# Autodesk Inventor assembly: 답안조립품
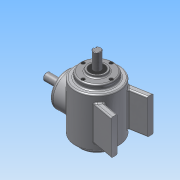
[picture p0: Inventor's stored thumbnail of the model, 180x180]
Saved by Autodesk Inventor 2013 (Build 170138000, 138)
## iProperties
Created: 2015-01
Part Number: 답안조립품
Document SubType Name: Assembly
Designer: Administrator
Author: Administrator
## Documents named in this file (15)
- C:\Users\Administrator\Desktop\450106V1009\답안조립품.iam
- C:\Users\Administrator\Desktop\450106V1009\1-본체.ipt
- C:\Users\Administrator\Desktop\450106V1009\커버.ipt
- C:\Users\Administrator\Desktop\450106V1009\베어링 6203.ipt
- C:\Users\Administrator\Desktop\450106V1009\서브 축.ipt
- 서브 축.ipt
- C:\Users\Administrator\Desktop\450106V1009\키 4x4.ipt
- C:\Users\Administrator\Desktop\450106V1009\서브 베벨기어.ipt
- C:\Users\Administrator\Desktop\450106V1009\메인 축.ipt
- 메인 축.ipt
- C:\Users\Administrator\Desktop\450106V1009\키 5x5.ipt
- C:\Users\Administrator\Desktop\450106V1009\메인 베벨기어.ipt
- C:\Users\Administrator\Desktop\450106V1009\커버2.ipt
- C:\Users\Administrator\Desktop\450106V1009\오일실.ipt
- C:\Users\Administrator\Desktop\450106V1009\M4.ipt
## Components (13 placed, 2 different names)
1. 1-본체:1
2. M4:1
3. M4:2
4. M4:3
5. M4:4
6. M4:5
7. M4:6
8. M4:7
9. M4:8
10. M4:9
11. M4:10
12. M4:11
13. M4:12
